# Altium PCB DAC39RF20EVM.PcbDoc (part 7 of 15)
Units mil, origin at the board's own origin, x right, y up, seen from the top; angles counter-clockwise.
Board outline 6200 x 2716.54 mil, 16 copper layers (Top Layer, L2 GND, L3 PWR, L4 GND, L5 PWR, L6 GND, L7 SIG, L8 GND, L9 GND, L10 SIG, L11 GND, L12 PWR, L13 GND, L14 PWR, L15 GND, Bottom Layer), stack 76.97 mil thick; 766 components, 495 nets, 3414 pads, 2373 vias.
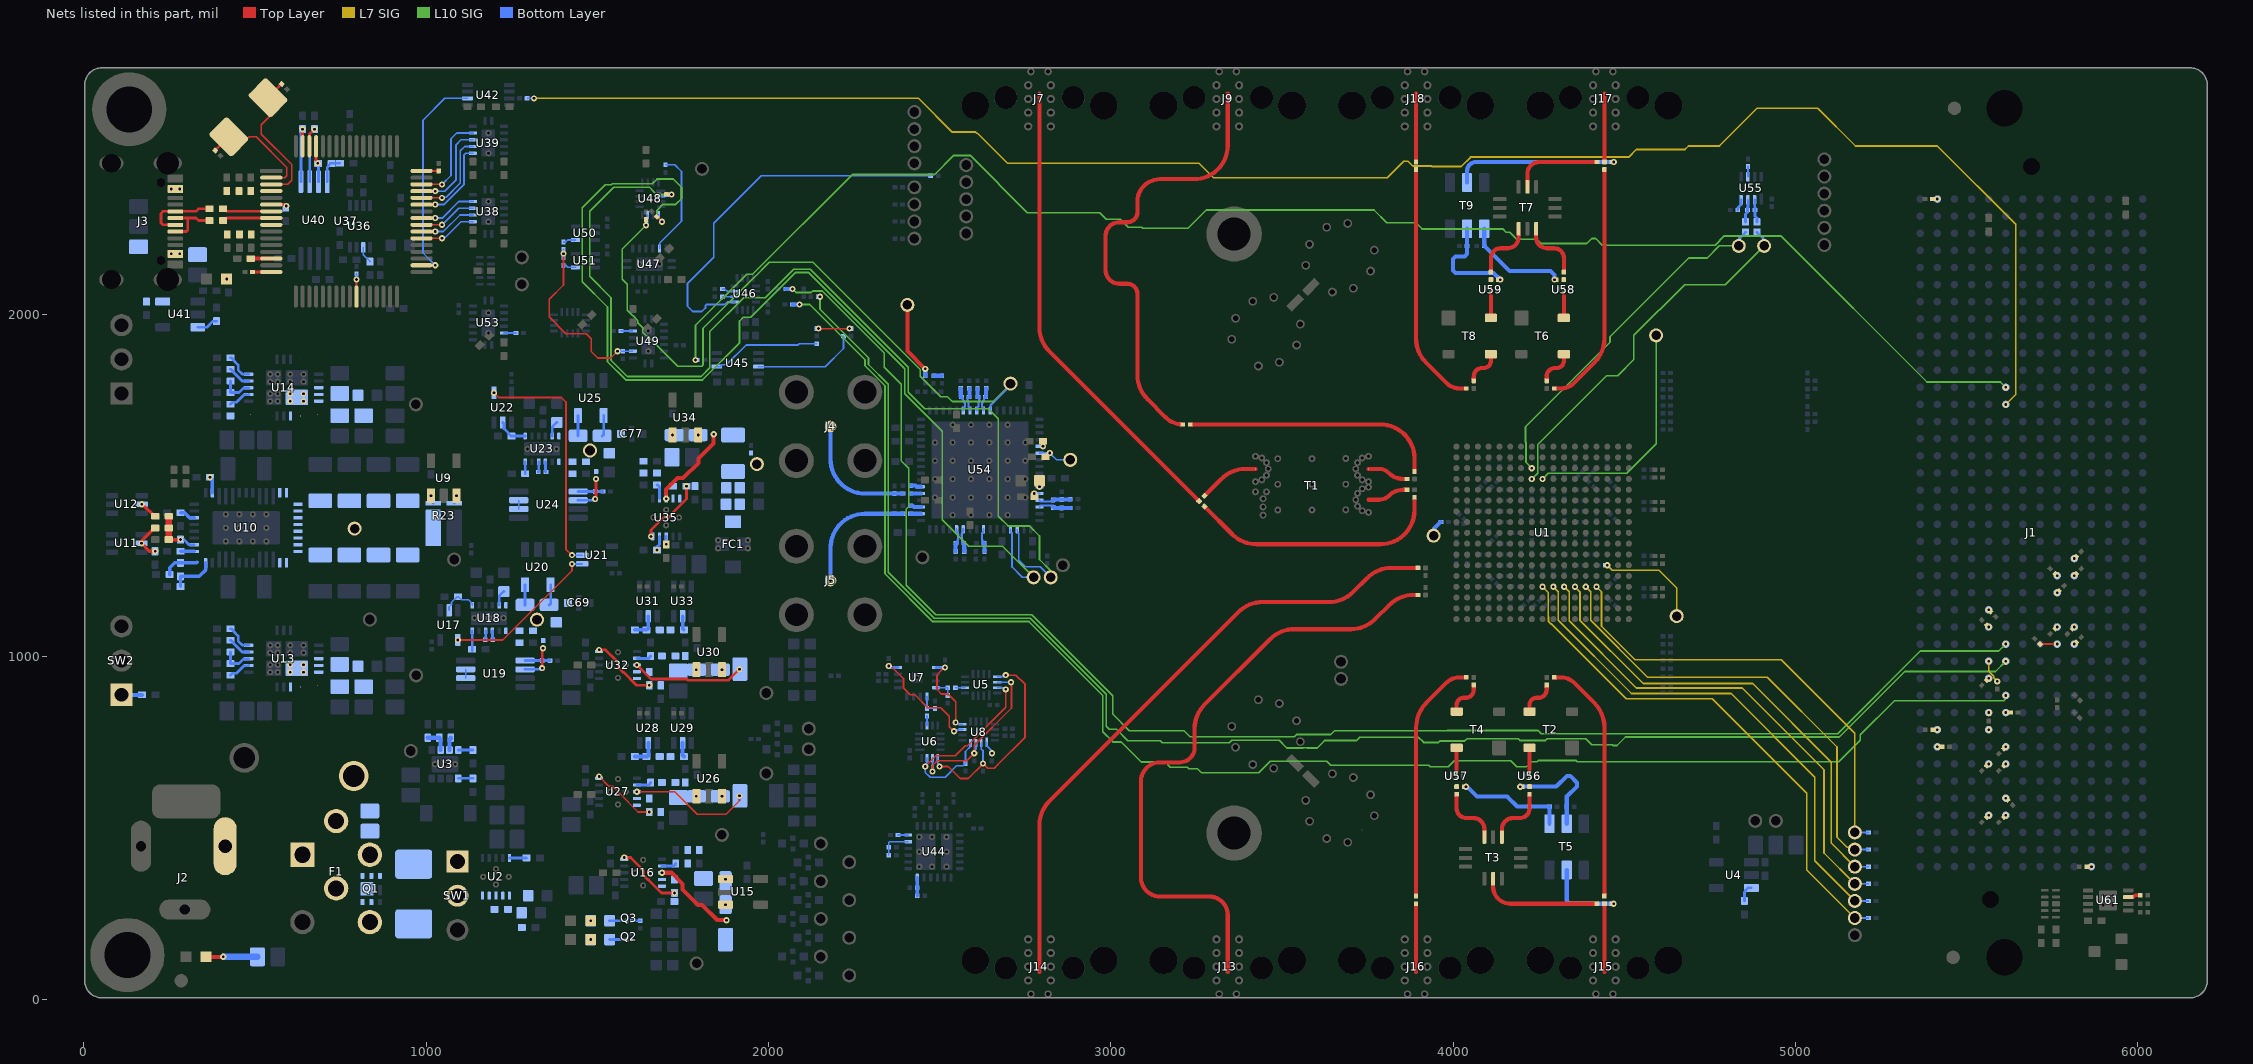
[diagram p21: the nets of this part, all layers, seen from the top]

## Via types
v1: diameter 18, hole 8, Top Layer to Bottom Layer, tented both sides, 2344 vias
v2: diameter 24, hole 12, Top Layer to Bottom Layer, tented both sides, 19 vias
v3: diameter 18, hole 8, Top Layer to Bottom Layer, tented bottom, 9 vias
v4: diameter 20, hole 10, Top Layer to Bottom Layer, tented both sides, 1 vias

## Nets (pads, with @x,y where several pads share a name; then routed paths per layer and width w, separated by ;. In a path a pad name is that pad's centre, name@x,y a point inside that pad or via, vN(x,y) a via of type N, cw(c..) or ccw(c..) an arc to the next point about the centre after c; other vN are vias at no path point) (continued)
LMK_DCLKOUT4_P: C166.2 R162.1 U54.24 | length 68.4
  Bottom Layer w6.3: R162.1@2627.86,1333.16 2626.85,1334.18 cw(c2630.65,1337.98) 2625.27,1337.98 2625.27,1339.13 ccw(c2621.96,1339.13) 2624.3,1341.47 cw(c2626.64,1343.81) 2623.33,1343.81 2623.33,1357.7 cw(c2631.34,1357.7) 2625.68,1363.37 ccw(c2620.02,1369.03) 2628.03,1369.03 U54.24@2628.03,1372.6
  Bottom Layer w12.1: R162.1@2627.87,1333.15 cw(c2621.01,1326.3) 2630.71,1326.3 C166.2@2630.71,1307.6
LMK_DCLKOUT6_N: C169.2 R163.2 U54.28 | length 68.2
  Bottom Layer w6.3: U54.28@2549.29,1372.6 2549.29,1369.03 ccw(c2557.3,1369.03) 2551.63,1363.37 cw(c2545.97,1357.7) 2553.98,1357.7 2553.98,1343.81 cw(c2550.67,1343.81) 2553.01,1341.47 ccw(c2555.35,1339.13) 2552.04,1339.13 2552.04,1337.98 cw(c2546.67,1337.98) R163.2@2550.47,1334.18
  Bottom Layer w12.1: C169.2@2546.61,1307.6 2546.61,1324.84 cw(c2559.81,1324.84) R163.2@2550.47,1334.18
LMK_DCLKOUT6_P: C168.2 R163.1 U54.27 | length 68.4
  Bottom Layer w6.3: R163.1@2568.81,1333.16 2567.79,1334.18 cw(c2571.59,1337.98) 2566.22,1337.98 2566.22,1339.13 ccw(c2562.91,1339.13) 2565.25,1341.47 cw(c2567.59,1343.81) 2564.28,1343.81 2564.28,1357.7 cw(c2572.29,1357.7) 2566.63,1363.37 ccw(c2560.96,1369.03) 2568.97,1369.03 U54.27@2568.97,1372.6
  Bottom Layer w12.1: R163.1@2568.81,1333.15 cw(c2561.96,1326.3) 2571.65,1326.3 C168.2@2571.65,1307.6
LMK_DCLKOUT10_N: C173.2 R164.2 U54.55 | length 70.6
  Bottom Layer w6.3: R164.2@2585.23,1759.06 2584.7,1759.06 2581.55,1755.91 2581.55,1747 2583.96,1744.59 2583.96,1730.64 2588.66,1725.95 U54.55@2588.66,1719.06
  Bottom Layer w12.1: R164.2@2585.23,1759.06 ccw(c2585.23,1760.56) 2586.73,1760.56 C173.2@2586.73,1784.06
LMK_DCLKOUT10_P: C172.2 R164.1 U54.54 | length 72.4
  Bottom Layer w6.3: R164.1@2563.58,1759.06 2563.97,1759.06 2567.12,1755.91 2567.12,1751.16 2571.25,1747.03 2571.25,1742.73 2573.66,1740.32 2573.66,1730.64 2568.97,1725.95 U54.54@2568.97,1719.06
  Bottom Layer w12.1: C172.2@2561.29,1784.06 2561.29,1760.95 ccw(c2563.18,1760.95) R164.1@2563.18,1759.06
LMK_SCLK: PP32.1 R142.1 U48.2 U54.19 | length 3121
  Top Layer w5: R142.1@1701.73,2350.62 v1(1716.73,2350.62)
  L10 SIG w5: v1(1716.73,2350.62) 1672.05,2350.62 1668.11,2354.56 1668.11,2355.69 1652.43,2371.37 1547.97,2371.37 1477.62,2301.02 1477.62,2111.24 1540.07,2048.79 1540.07,1866.08 1587.42,1818.73 1803.09,1818.73 1828.64,1844.29 1828.64,1950.25 1927.18,2048.79 1990.72,2048.79 2074.19,2132.26 2121.64,2132.26 2408.11,1845.79 2408.11,1772.88 2456.12,1724.87 2641.38,1724.87 2671.06,1695.18 2671.06,1410.97 2699.71,1382.33 2761.8,1382.33 2791.41,1352.72 2791.41,1284.15 2824.32,1251.24 PP32.1@2824.32,1232.14
  Bottom Layer w5: U48.2@1686.73,2345.62 1708.21,2345.62 1713.21,2350.62 v1(1716.73,2350.62) ; U54.19@2726.45,1372.6 2726.45,1365.71 2730.8,1361.37 2730.8,1282.26 2750.35,1262.71 2793.76,1262.71 PP32.1@2824.32,1232.14
LMK_SDCLKOUT1_N: C163.2 R158.2 R160.2 U54.14 | length 97.8
  Bottom Layer w6.3: U54.14@2791.41,1437.56 cw(c2795.35,1437.56) 2795.35,1441.5 2826.29,1441.5 cw(c2826.29,1436.38) 2831.29,1437.49 cw(c2826.29,1436.38) R158.2@2831.41,1436.38
  Bottom Layer w12.1: R158.2@2829.84,1438.74 ccw(c2839.17,1448.09) 2831.29,1437.49 ccw(c2839.17,1448.09) 2839.17,1434.88 C163.2@2881.41,1434.88
LMK_SDCLKOUT1_P: C162.2 R158.1 R159.2 U54.13 | length 97.8
  Bottom Layer w6.3: U54.13@2791.41,1457.25 ccw(c2795.35,1457.25) 2795.35,1453.3 2826.29,1453.3 ccw(c2826.29,1458.43) 2831.29,1457.32 ccw(c2826.29,1458.43) R158.1@2831.41,1458.43
  Bottom Layer w12.1: R158.1@2829.84,1456.07 cw(c2839.16,1446.74) 2831.29,1457.32 cw(c2839.16,1446.74) 2839.06,1459.93 cw(c2839.16,1446.74) 2839.16,1459.93 R159.2@2856.41,1459.93 C162.2@2881.41,1459.93
LMK_SDCLKOUT11_N: C175.2 R165.1 U54.57 | length 72.4
  Bottom Layer w6.3: U54.57@2628.03,1719.06 2628.03,1725.95 2623.33,1730.64 2623.33,1740.32 2625.75,1742.73 2625.75,1747.03 2629.88,1751.16 2629.88,1755.91 2633.03,1759.06 R165.1@2633.42,1759.06
  Bottom Layer w12.1: R165.1@2633.81,1759.06 ccw(c2633.81,1760.95) 2635.71,1760.95 C175.2@2635.71,1784.06
LMK_SDCLKOUT11_P: C174.2 R165.2 U54.56 | length 70.6
  Bottom Layer w6.3: U54.56@2608.34,1719.06 2608.34,1725.95 2613.03,1730.64 2613.03,1744.59 2615.45,1747 2615.45,1755.91 2612.3,1759.06 R165.2@2611.77,1759.06
  Bottom Layer w12.1: C174.2@2610.27,1784.06 2610.27,1760.56 ccw(c2611.77,1760.56) R165.2@2611.77,1759.06
LMK_SDI: PP33.1 R143.1 U48.5 U54.20 | length 3203.6
  Top Layer w5: R143.1@1673.86,2285.51 v1(1688.86,2270.51)
  L10 SIG w5: v1(1688.86,2270.51) 1674.51,2284.85 1674.51,2304.32 1691.57,2321.38 1729.38,2321.38 1745.94,2337.94 1745.94,2371.37 1721.87,2395.44 1674.51,2395.44 1660.45,2381.37 1543.83,2381.37 1541.39,2378.94 1522.97,2378.94 1456.1,2312.06 1456.1,2095.26 1529.79,2021.57 1529.79,1862.22 1583.27,1808.73 1807.23,1808.73 1915.46,1916.97 1915.46,1980.9 1926.52,1991.96 1948.03,1991.96 2078.33,2122.26 2117.5,2122.26 2398.11,1841.65 2398.11,1768.73 2507.7,1659.14 2507.7,1399.79 2584.39,1323.1 2683.36,1323.1 PP33.1@2774.32,1232.14
  Bottom Layer w5: U48.5@1678.86,2290.51 1678.86,2282.63 1688.86,2272.63 v1(1688.86,2270.51) ; U54.20@2706.77,1372.6 2706.77,1365.71 2711.11,1361.37 2711.11,1262.59 2741.56,1232.14 PP33.1@2774.32,1232.14
LMK_SDO: PP34.1 R144.1 U48.7 U54.58 | length 2026
  Top Layer w6.3: v1(1642.36,2260.51) R144.1@1642.36,2277.26
  L10 SIG w5: v1(1642.36,2260.51) 1642.1,2260.51 1572.89,2191.3 1572.89,2102.91 1587.39,2088.41 1587.39,2011.71 1603.01,1996.1 1604.65,1996.1 1618.33,1982.42 1618.33,1975.39 1632.44,1961.29 1632.44,1947.98 1643.13,1937.29 1645.59,1937.29 1734.45,1848.43 1804.5,1848.43 1808.64,1852.57 1808.64,1959.55 1956.54,2107.45 1957.55,2107.45 2002.37,2152.26 2129.93,2152.26 2443.17,1839.02 2443.17,1819.28 2502.89,1759.56 2522.63,1759.56 2536.66,1745.52 2655.61,1745.52 2706.77,1796.68 PP34.1@2706.77,1798.03
  Bottom Layer w5: v1(1642.36,2260.51) 1642.36,2264.02 1647.36,2269.02 U48.7@1647.36,2290.51
  Bottom Layer w6.3: U54.58@2647.71,1719.06 2648.23,1719.57 2648.23,1734.89 2706.77,1793.43 PP34.1@2706.77,1798.03
NetC1_1: C1.1 D2.2 F1.2 Q1.3 SW1.1
NetC1_2: C1.2 D2.1 F1.4 Q1.1 Q1.2 Q1.5 Q1.6 Q1.8
NetC4_2: C4.2 R1.1 R4.2 U2.2
NetC5_2: C5.2 U2.1
NetC10_2: C10.2 U3.8 | length 43
  Bottom Layer w8: U3.8@1093.48,727.63 C10.2@1136.48,727.63
NetC11_1: C11.1 R12.2 U7.4 | length 58
  Bottom Layer w5: U7.4@2488.63,909.89 R12.2@2523.63,909.89 C11.1@2523.63,886.89
NetC12_1: C12.1 R16.2 U7.5 | length 58
  Bottom Layer w5: U7.5@2463.04,884.3 R16.2@2463.04,849.3 C12.1@2486.04,849.3
NetC22_2: C22.2 C23.2 C24.2 C25.2 C27.2 C28.2 C29.2 C30.2 PP10.1 R23.4 U10.13 U10.14 U10.15 U10.16 U10.17 U10.18 U10.19 U10.20 U10.21 U10.22 U10.23 U10.24 U10.25 U10.26
NetC26_2: C26.2 U10.39 | length 40.3
  Bottom Layer w10: C26.2@282.52,1308.34 294.33,1308.34 294.98,1307.69 U10.39@322.52,1307.69
NetC31_2: C31.2 U10.44 | length 46.2
  Bottom Layer w10: C31.2@282.52,1420.71 294.33,1420.71 294.33,1420.53 308.74,1406.12 U10.44@322.52,1406.12
NetC34_2: C34.2 C35.2 C36.2 FB1.1 U13.10 U13.11 U13.12 U13.13 U13.14 U13.15 U13.27
NetC39_1: C39.1 U13.21 | length 64.7
  Bottom Layer w8: C39.1@428.75,946.11 434.53,951.9 445.59,951.9 467.5,973.81 480.64,973.81 U13.21@481.56,974.73
NetC42_2: C42.2 C43.2 C44.2 FB2.1 U14.10 U14.11 U14.12 U14.13 U14.14 U14.15 U14.27
NetC47_1: C47.1 U14.21 | length 64.7
  Bottom Layer w8: C47.1@428.75,1737.64 434.53,1743.42 445.59,1743.42 467.5,1765.34 480.64,1765.34 U14.21@481.56,1766.26
NetC52_2: C52.2 R46.1 R47.2 U15.1 U16.9 U16.10
  other v1: 1874.64,350.61
NetC58_2: C58.2 R49.2 U16.7 | length 44
  Bottom Layer w9: U16.7@1688.89,388.99 1723.55,388.99 1728.89,394.34 C58.2@1728.89,396.08
NetC68_1: C68.1 U18.10 | length 26.5
  Bottom Layer w8: C68.1@1172.67,1049.81 1172.67,1056.11 1173.86,1057.29 U18.10@1173.86,1075.81
NetC68_2: C68.2 U18.9 | length 26.5
  Bottom Layer w8: U18.9@1193.72,1075.81 1193.72,1057.29 1194.9,1056.11 C68.2@1194.9,1049.81
NetC69_1: C69.1 C70.2 PP23.1 R52.2 R53.2 R57.1 U20.4 | length 61.8
  Bottom Layer w8: R52.2@1359.26,1150.61 1363.59,1154.95 U20.4@1363.59,1210.61
NetC71_2: C71.2 U18.5 | length 46.4
  Bottom Layer w8: U18.5@1213.23,1150.61 1213.23,1174.18 1214.56,1175.52 1214.56,1178.87 1226.31,1190.61 C71.2@1227.3,1190.61
NetC76_1: C76.1 U23.10 | length 30.5
  Bottom Layer w8: C76.1@1327.49,1539.83 1328.67,1541.01 U23.10@1328.67,1569.83
NetC76_2: C76.2 U23.9 | length 30.5
  Bottom Layer w8: U23.9@1348.36,1569.83 1348.36,1541.01 C76.2@1349.54,1539.83
NetC77_1: C77.1 C78.2 PP24.1 R60.2 R61.2 R65.1 U25.4 | length 61.8
  Bottom Layer w8: R60.2@1514.07,1644.63 1518.4,1648.96 U25.4@1518.4,1704.63
NetC79_2: C79.2 U23.5 | length 46.4
  Bottom Layer w8: U23.5@1368.04,1644.63 1368.04,1668.19 1369.38,1669.53 1369.38,1672.88 1381.13,1684.63 C79.2@1382.11,1684.63
NetC84_2: C84.2 R70.1 R71.2 U26.1 U27.9 U27.10
  other v1: 1789.17,592.47
NetC90_2: C90.2 R72.1 R75.2 R77.2 U27.7 | length 44
  Bottom Layer w9: U27.7@1615.52,625.54 1650.18,625.54 1655.52,630.88 C90.2@1655.52,632.63
NetC94_2: C94.2 R83.1 R84.2 U30.1 U32.9 U32.10
  other v1: 1789.17,962.47
NetC99_2: C99.2 R80.1 R85.2 R87.2 U32.7 | length 44
  Bottom Layer w9: U32.7@1615.52,995.54 1650.18,995.54 1655.52,1000.88 C99.2@1655.52,1002.63
NetC107_2: C107.2 R92.1 R93.2 U34.1 U35.9 U35.10
  other v1: 1719.79,1647.65
NetC108_2: C108.2 C109.2 C110.2 C111.2 FB6.2 FC1.1 PP29.1 R89.1
NetC112_2: C112.2 R95.2 U35.7 | length 44
  Bottom Layer w9: C112.2@1674.32,1501.9 1676.06,1501.9 1681.4,1496.56 U35.7@1681.4,1461.9
NetC114_2: C114.2 C115.2 FB7.2 U37.9
NetC116_2: C116.2 C117.2 FB8.2 U37.4
NetC129_2: C129.2 U37.2 Y1.1 | length 338.6
  Top Layer w5: Y1.1@423.71,2518.95 428.71,2513.95 478.07,2513.95 483.07,2518.95 503.21,2518.95 592.88,2429.29 592.88,2405.47 586.97,2399.56 U37.2@547.59,2399.56
  Top Layer w8: C129.2@383.71,2478.95 Y1.1@423.71,2518.95
NetC130_2: C130.2 U37.3 Y1.2 | length 411.4
  Top Layer w5: Y1.2@537.85,2633.09 542.85,2628.09 542.85,2578.73 518.5,2554.38 518.5,2526.75 607.21,2438.03 607.21,2391.69 595.4,2379.88 U37.3@547.59,2379.88
  Top Layer w8: Y1.2@537.85,2633.09 C130.2@577.85,2673.09
NetC133_2: C133.2 R115.2 U41.5
NetC160_1: C160.1 J4.1 R157.2 | length 364.7
  Bottom Layer w12.1: v1(2181.22,1672.88) 2181.22,1576.93 ccw(c2281.22,1576.93) 2281.22,1476.93 R157.2@2367.91,1476.93 C160.1@2392.91,1476.93
NetC160_2: C160.2 U54.37 | length 30
  Bottom Layer w12.1: C160.2@2414.96,1476.93 U54.37@2444.96,1476.93
NetC161_2: C161.2 U54.38 | length 31.4
  Bottom Layer w12.1: C161.2@2414.96,1499.98 2429.78,1499.98 2433.14,1496.62 U54.38@2444.96,1496.62
NetC164_2: C164.2 U54.35 | length 31.4
  Bottom Layer w12.1: C164.2@2414.96,1440.92 2422.04,1440.92 2425.4,1437.56 U54.35@2444.96,1437.56
NetC165_1: C165.1 J5.1 R161.2 | length 363.8
  Bottom Layer w12.1: v1(2181.22,1222.88) 2181.22,1317.88 cw(c2281.22,1317.88) 2281.22,1417.88 R161.2@2367.91,1417.88 C165.1@2392.91,1417.88
NetC165_2: C165.2 U54.34 | length 30
  Bottom Layer w12.1: C165.2@2414.96,1417.88 U54.34@2444.96,1417.88
NetC170_1: C170.1 PP40.1 | length 228.3
  Top Layer w12.1: PP40.1@2405.59,2027.82 2405.59,1893.19 v1(2457.67,1841.11)
  Bottom Layer w12.1: C170.1@2457.67,1821.11 v1(2457.67,1841.11)
NetC171_1: C171.1 R168.2 | length 25
  Bottom Layer w12.1: C171.1@2481.85,1821.11 R168.2@2506.85,1821.11
NetC176_2: C176.2 U54.11 | length 18
  Top Layer w10: v1(2791.41,1496.62) 2791.41,1514.36 C176.2@2791.7,1514.36
NetC177_1: C177.1 U54.12 | length 24.7
  Top Layer w6.3: v1(2776.41,1476.93) cw(c2776.41,1475.97) 2777.37,1475.97 C177.1@2777.37,1467.83
  Bottom Layer w6.3: v1(2776.41,1476.93) U54.12@2791.41,1476.93
NetC182_1: C182.1 C183.1 | length 742.1
  Top Layer w12.1: 3354.38,1357.99 ccw(c3425.1,1428.7) 3425.1,1328.7 3786.85,1328.7
  Top Layer w12.3: C182.1@3273.32,1439.06 3354.38,1357.99 ; 3786.85,1328.7 ccw(c3786.85,1428.7) 3886.85,1428.7 C183.1@3886.85,1458.82
NetC182_2: C182.2 C184.2 J7.1 | length 1379.3
  Top Layer w12.1: J7.1@2791.51,2645.14 2791.51,1962.29 ccw(c2891.51,1962.29) 2820.8,1891.58 C182.2@3257.73,1454.65
NetC184_1: C184.1 T1.1 | length 177.4
  Top Layer w12.3: C184.1@3273.32,1470.24 3322.49,1519.41 cw(c3393.2,1448.7) 3393.2,1548.7 T1.1@3422.48,1548.7
NetC186_2: C186.2 T1.2 | length 120.1
  Top Layer w12.1: T1.2@3752.71,1458.7 3783.45,1458.7 ccw(c3783.45,1498.96) 3811.92,1470.49 cw(c3854.07,1428.34) 3854.07,1487.95 C186.2@3864.8,1487.95 C186.2@3865.04,1487.95
NetC190_2: C190.2 T1.3 | length 120.1
  Top Layer w12.1: T1.3@3752.48,1548.7 3783.22,1548.7 cw(c3783.22,1508.44) 3811.68,1536.91 ccw(c3853.84,1579.06) 3853.84,1519.45 C190.2@3864.8,1519.45
NetC192_1: C192.1 C197.1 | length 749.2
  Top Layer w12.1: C197.1@3232.04,1678.7 3665.6,1678.7
  Top Layer w12.3: 3665.6,1678.7 3786.98,1678.7 cw(c3786.98,1578.7) 3886.98,1578.7 C192.1@3886.98,1548.58 ; C192.1@3886.85,1541.5 C192.1@3886.85,1548.58
NetC197_2: C197.2 J9.1 | length 1351
  Top Layer w12.1: C197.2@3209.99,1678.7 cw(c3209.99,1749.79) 3159.72,1699.52 3106.8,1752.44 cw(c3177.51,1823.16) 3077.51,1823.16 3077.51,2060.35 ccw(c3048.22,2060.35) 3048.22,2089.64 3024.6,2089.64 cw(c3024.6,2129.64) 2984.6,2129.64 2984.6,2229.4 cw(c3024.6,2229.4) 3024.6,2269.4 3048.22,2269.4 ccw(c3048.22,2298.69) 3077.51,2298.69 3077.51,2329.31 cw(c3143.34,2329.31) 3143.34,2395.14 3243.01,2395.14 ccw(c3243.01,2493.64) 3341.51,2493.64 J9.1@3341.51,2645.14
NetC218_1: C218.1 R180.2 U55.3 | length 84.7
  Bottom Layer w5: C218.1@4859.56,2305.14 4859.56,2320.18 4860.74,2321.36 U55.3@4860.74,2335.14
  Bottom Layer w8: R180.2@4853.56,2270.14 4853.56,2292.84 4859.56,2298.84 C218.1@4859.56,2305.14 4859.56,2311.44 4860.74,2312.62 U55.3@4860.74,2321.36
NetC218_2: C218.2 R178.2 U55.2 | length 68
  Bottom Layer w8: U55.2@4880.43,2335.14 4880.43,2312.62 4881.61,2311.44 C218.2@4881.61,2305.14 4881.61,2287.16 4887.61,2281.16 R178.2@4887.61,2270.14
NetC220_1: C220.1 T3.1 | length 179.8
  Top Layer w12.1: T3.1@4142.1,473.58 4142.1,496.84 cw(c4174.03,496.84) 4174.03,528.77 4194.14,528.77 ccw(c4194.14,557.64) 4223.02,557.64 C220.1@4223.02,598.58
NetC220_2: C220.2 C222.2 U56.2
NetC221_1: C221.1 C223.1 J15.1 R184.1 | length 200
  Top Layer w12.1: J15.1@4441.51,78.8 C221.1@4441.51,278.8
NetC221_2: C221.2 T3.8 | length 354.2
  Top Layer w12.1: T3.8@4116.51,351.54 4116.51,328.8 ccw(c4166.51,328.8) 4166.51,278.8 C221.2@4419.46,278.8
NetC222_1: C222.1 C227.1 T5.2 | length 323.6
  Top Layer w8: v1(4195.97,620.63) C222.1@4200.97,620.63
  Bottom Layer w12.1: v1(4195.97,620.63) 4300.83,620.63 4331.88,651.69 4341.91,651.69 4361.48,632.11 4361.48,621.55 4331.48,591.55 C227.1@4331.48,562.45 T5.2@4331.48,512.45
NetC223_2: C223.2 T5.5 | length 235.3
  Top Layer w8: C223.2@4463.56,278.8 v1(4468.56,278.8)
  Bottom Layer w12.1: T5.5@4331.48,377.41 4331.48,291.39 ccw(c4344.08,291.39) 4344.08,278.8 v1(4468.56,278.8)
NetC224_1: C224.1 T3.3 | length 179.8
  Top Layer w12.1: C224.1@4010,598.58 4010,557.64 ccw(c4038.87,557.64) 4038.87,528.77 4058.99,528.77 cw(c4058.99,496.84) 4090.92,496.84 T3.3@4090.92,473.58
NetC224_2: C224.2 C225.2 U57.2
NetC225_1: C225.1 C226.1 T5.1 | length 323.5
  Top Layer w8: C225.1@4032.05,620.63 v1(4037.05,620.63)
  Bottom Layer w12.1: v1(4037.05,620.63) 4038.64,620.63 4041.59,617.68 4043.53,617.68 4069.5,591.71 4157.61,591.71 4186.88,562.45 C226.1@4281.48,562.45 T5.1@4281.48,512.45
NetC228_1: C228.1 T7.3 | length 179.8
  Top Layer w12.1: T7.3@4242.1,2248.63 4242.1,2225.37 ccw(c4274.03,2225.37) 4274.03,2193.44 4294.14,2193.44 cw(c4294.14,2164.57) 4323.02,2164.57 C228.1@4323.02,2123.63
NetC228_2: C228.2 C230.2 U58.2
NetC229_1: C229.1 C231.1 J17.1 R190.1 | length 199.8
  Top Layer w12.1: C229.1@4441.51,2445.37 4441.51,2475.37 J17.1@4441.51,2645.14
NetC229_2: C229.2 T7.8 | length 260.9
  Top Layer w12.1: T7.8@4216.51,2372.26 4216.51,2410.9 cw(c4250.74,2410.9) 4250.74,2445.14 4389.23,2445.14 C229.2@4419.23,2445.14
NetC230_1: C230.1 C235.1 T9.1 | length 309.1
  Top Layer w8: v1(4295.74,2101.58) C230.1@4300.74,2101.58
  Bottom Layer w12.1: T9.1@4090.52,2250.1 C235.1@4090.52,2200.1 4091.31,2200.1 4164.89,2126.52 4284.54,2126.52 4295.51,2115.55 4295.51,2101.81 v1(4295.74,2101.58)
NetC231_2: C231.2 T9.5 | length 482.1
  Top Layer w8: C231.2@4463.79,2445.14 v1(4468.79,2445.14)
  Bottom Layer w12.1: T9.5@4040.52,2385.14 4040.52,2419.23 cw(c4066.43,2419.23) 4066.43,2445.14 v1(4468.79,2445.14)
NetC232_1: C232.1 T7.1 | length 179.8
  Top Layer w12.1: C232.1@4110,2123.63 4110,2164.57 cw(c4138.87,2164.57) 4138.87,2193.44 4158.99,2193.44 ccw(c4158.99,2225.37) 4190.92,2225.37 T7.1@4190.92,2248.63
NetC232_2: C232.2 C233.2 U59.2
NetC233_1: C233.1 C234.1 T9.2 | length 308.7
  Top Layer w8: C233.1@4132.28,2101.58 v1(4137.28,2101.58)
  Bottom Layer w12.1: T9.2@4040.52,2250.1 C234.1@4040.52,2200.1 4040.52,2176.18 4033.44,2169.09 4006.47,2169.09 3999.38,2162 3999.38,2128.08 4006.47,2120.99 4117.87,2120.99 v1(4137.28,2101.58)
NetD1_2: D1.2 R3.2 | length 150
  Top Layer w12: D1.2@357.27,123.65 v1(407.27,123.65)
  Bottom Layer w18: v1(407.27,123.65) R3.2@507.27,123.65
NetD4_2: D4.2 R108.2 | length 5
  Bottom Layer w12.1: v1(417.59,2103.8) R108.2@422.59,2103.8
NetD6_1: D6.1 R235.1
  other v1: 1480.75,174.11
NetD7_1: D7.1 R236.1
  other v1: 1480.75,229.11
NetF1_1: F1.1 J2.1 TP1.1
NetFB3_1: FB3.1 R46.2 U15.3 U16.8 | length 255.5
  Top Layer w12: v1(1688.82,369.31) 1716.19,369.31 1748.9,336.6 1748.9,320.03 1793.58,275.35 1806.26,275.35 1850.23,231.38 1875.85,231.38 v1(1877,230.23)
  other v1: 1874.64,275.81
NetFB4_1: FB4.1 R70.2 U26.3 U27.8 | length 357.3
  Top Layer w5: v1(1615.45,605.86) 1726.13,605.86 1791.54,540.44 1875.85,540.44 1915.52,580.11 v1(1915.52,593.85)
  other v1: 1863.97,592.47
NetFB5_1: FB5.1 R83.2 U30.3 U32.8 | length 331.6
  Top Layer w8: v1(1615.45,975.86) 1656.51,934.8 1761.05,934.8 1764.03,931.82 1883.49,931.82 v1(1915.52,963.85)
  other v1: 1863.97,962.47
NetFB6_1: FB6.1 R92.2 U34.3 U35.8 | length 255.5
  Top Layer w12: v1(1701.09,1461.83) 1701.09,1489.2 1733.8,1521.91 1750.36,1521.91 1795.05,1566.59 1795.05,1579.27 1839.01,1623.24 1839.01,1648.86 v1(1840.16,1650.01)
  other v1: 1794.59,1647.65
NetJ1_B40: J1.B40 R198.2 | length 13.3
  Top Layer w10: R198.2@5850.72,387.07 v1(5864.01,387.07)
NetJ1_C22: J1.C22 R199.2 | length 6.7
  Top Layer w5: v1(5814.01,1287.07) R199.2@5818.72,1291.77
NetJ1_C23: J1.C23 R201.2 | length 6.7
  Top Layer w5: v1(5814.01,1237.07) R201.2@5818.72,1241.77
NetJ1_C26: J1.C26 R204.2 | length 6.7
  Top Layer w5: R204.2@5809.31,1082.36 v3(5814.01,1087.07)
NetJ1_C27: J1.C27 R206.2 | length 6.7
  Top Layer w5: v3(5814.01,1037.07) R206.2@5818.72,1041.77
NetJ1_D23: J1.D23 R200.2 | length 7.1
  Top Layer w5: R200.2@5759.31,1241.77 v1(5764.01,1237.07) v1@5764.32,1236.76
NetJ1_D24: J1.D24 R202.2 | length 6.7
  Top Layer w5: v1(5764.01,1187.07) R202.2@5768.72,1191.77
NetJ1_D26: J1.D26 R203.2 | length 6.7
  Top Layer w5: R203.2@5759.31,1082.36 v3(5764.01,1087.07)
NetJ1_D27: J1.D27 R205.2 | length 50
  Top Layer w5: R205.2@5714.01,1037.07 v3(5764.01,1037.07)
NetJ1_G12: J1.G12 R210.2 | length 4497.7
  L10 SIG w5: v1(1786.93,1867.08) 1786.93,1968.28 1936.09,2117.45 1953.41,2117.45 2244.41,2408.45 2484.86,2408.45 2540.87,2464.45 2589.11,2464.45 2756.22,2297.34 2967.66,2297.34 2986.89,2278.11 3027.15,2278.11 3051.02,2254.24 3090.17,2254.24 3092.64,2251.77 3225.09,2251.77 3278.31,2304.98 3768.69,2304.98 3805.48,2268.2 3890.42,2268.2 3908.78,2249.84 4144.47,2249.84 4154.29,2240.02 4164.91,2240.02 4185.42,2219.51 4244.48,2219.51 4256.73,2207.26 4389.98,2207.26 4404.48,2221.77 4416.5,2221.77 4435.78,2202.49 4765.25,2202.49 4792.08,2229.32 4957.1,2229.32 5383.62,1802.8 5598.28,1802.8 v1(5614.01,1787.07)
  Bottom Layer w8: v1(1786.93,1867.08) R210.2@1791.93,1867.08
NetJ1_G13: J1.G13 R211.2 | length 5219.4
  L7 SIG w5: v1(1314.92,2631.1) 2437.99,2631.1 2536.43,2532.66 2604.56,2532.66 2608.12,2529.1 2610.38,2529.1 2698.15,2441.34 3257.52,2441.34 3299.59,2399.27 3306.32,2399.27 3306.4,2399.34 3807.64,2399.34 3855.87,2447.57 3867.88,2447.57 3881.97,2433.49 3936.46,2433.49 3937.83,2432.11 4023.19,2432.11 4050.71,2459.64 4512.94,2459.64 4535.37,2482.07 4677.11,2482.07 4687.11,2492.07 4777.45,2492.07 4887.45,2602.07 5064.84,2602.07 5174.84,2492.07 5414.01,2492.07 5643.09,2262.99 5643.09,1766.14 v3(5614.01,1737.07)
  Bottom Layer w5: R211.2@1294.92,2631.1 v1(1314.92,2631.1)
NetJ1_G27: J1.G27 R212.2 | length 4626
  L10 SIG w5: v1(2070.2,2074.43) 2080.25,2064.37 2124.97,2064.37 2128.92,2068.33 2157.29,2068.33 2338.39,1887.23 2338.39,1845.52 2388.11,1795.8 2388.11,1571.77 2409.41,1550.48 2409.41,1439.09 2401.94,1431.62 2401.94,1209.24 2488.3,1122.88 2768.95,1122.88 3005.65,886.18 3005.65,832.71 3054.17,784.19 3213.52,784.19 3231.06,766.64 3535.9,766.64 3542.01,772.75 3641.53,772.75 3653.08,784.3 3843.95,784.3 3844.2,784.05 3982.67,784.05 3983.38,784.76 4248.3,784.76 4257.47,775.59 5122.99,775.59 5364.13,1016.73 5593.67,1016.73 v1(5614.01,1037.07)
  Bottom Layer w12: R212.2@2050.2,2074.43 v1(2070.2,2074.43)
NetJ1_G28: J1.G28 R213.2 | length 4567.9
  L10 SIG w5: v1(2150.2,2051.83) 2150.2,2014.8 2291.99,1873.01 2291.99,1853.93 2350.13,1795.8 2350.13,1246.91 2484.16,1112.88 2764.81,1112.88 2986.61,891.08 2986.61,796.87 2995.1,788.37 3016.47,788.37 3049.65,755.19 3144.02,755.19 3149.97,749.23 3345.89,749.23 3352.7,756.04 3491.81,756.04 3514.08,733.78 3561.55,733.78 3561.93,734.16 3573.94,734.16 3574.33,733.78 3602.56,733.78 3624.02,755.24 3717.44,755.24 3727.25,765.05 3898.22,765.05 3913.38,749.89 3956.88,749.89 3961.3,754.32 4033.84,754.32 4040.12,760.59 4190.37,760.59 4195.2,755.76 4269.56,755.76 4274.39,760.59 4387.1,760.59 4404.48,743.21 4464.4,743.21 4466.52,741.09 4478.53,741.09 4503.03,765.59 5127.13,765.59 5318.46,956.92 5583.86,956.92 v1(5614.01,987.07)
  Bottom Layer w12: R213.2@2145.2,2051.83 v1(2150.2,2051.83)
NetJ1_G30: J1.G30 R214.2 | length 4644.5
  L10 SIG w5: v1(2090.2,2029.23) 2120.77,2029.23 2281.99,1868.01 2281.99,1849.79 2340.13,1791.65 2340.13,1242.77 2480.02,1102.88 2760.67,1102.88 2976.61,886.93 2976.61,780.86 3006.5,750.97 3030.61,750.97 3088.91,692.67 3158.43,692.67 3173.86,677.24 3223.82,677.24 3227.85,673.21 3252.97,673.21 3264.8,661.38 3431.73,661.38 3465.15,694.8 3630.23,694.8 3642.13,682.89 3928.77,682.89 3932.9,678.76 3984.99,678.76 4002.53,696.3 4168.45,696.3 4185.99,678.76 4214.24,678.76 4228.57,693.09 4244.81,693.09 4249.07,697.34 4358.11,697.34 4362.36,693.09 5126.39,693.09 5189.26,755.96 5189.26,771.82 5289.02,871.57 5608.2,871.57 5612.19,875.56 5612.19,885.24 v1(5614.01,887.07)
  Bottom Layer w12: R214.2@2070.2,2029.23 v1(2090.2,2029.23)
NetJ1_G31: J1.G31 R215.2 | length 13.9
  Top Layer w5: v1(5614.01,837.07) R215.2@5627.91,837.07
NetJ1_G33: J1.G33 R216.2 | length 6.7
  Top Layer w5: R216.2@5609.31,732.36 v1(5614.01,737.07)
NetJ1_G34: J1.G34 R217.2 | length 6.7
  Top Layer w5: R217.2@5609.31,682.36 v1(5614.01,687.07)
NetJ1_G36: J1.G36 R218.2 | length 6.7
  Top Layer w5: v1(5614.01,587.07) R218.2@5618.72,582.36
NetJ1_G37: J1.G37 R219.2 | length 6.7
  Top Layer w5: R219.2@5609.31,532.36 v1(5614.01,537.07)
NetJ1_H25: J1.H25 R221.2 | length 6.7
  Top Layer w5: v1(5564.01,1137.07) R221.2@5568.72,1132.36
NetJ1_H26: J1.H26 R222.2 | length 6.7
  Top Layer w5: R222.2@5559.31,1091.77 v1(5564.01,1087.07)
NetJ1_H28: J1.H28 R223.2 | length 69.2
  L7 SIG w5: v1(5564.01,987.07) 5564.01,957.57 5578.51,943.07 5578.51,938.78 5589.01,928.28 v1(5589.01,928.22)
NetJ1_H29: J1.H29 R224.2 | length 6.7
  Top Layer w5: R224.2@5559.31,932.36 v1(5564.01,937.07)
NetJ1_H31: J1.H31 R225.2
  other v1: 5564.01,837.07
NetJ1_H32: J1.H32 R226.2
  other v1: 5564.01,787.07
NetJ1_H34: J1.H34 R227.2 | length 6.7
  Top Layer w5: R227.2@5559.31,682.36 v1(5564.01,687.07)
NetJ1_H37: J1.H37 R228.2 | length 6.7
  Top Layer w5: R228.2@5559.31,532.36 v1(5564.01,537.07)
NetJ1_L1: J1.L1 R230.2 | length 14
  Top Layer w10: R230.2@5400.04,2337.07 v1(5414.01,2337.07)
NetJ1_L32: J1.L32 R231.2 | length 13.3
  Top Layer w10: R231.2@5400.72,787.07 v1(5414.01,787.07)
NetJ1_L33: J1.L33 R232.2 | length 14
  Top Layer w10: v1(5414.01,737.07) R232.2@5427.99,737.07
NetJ3_A4,B4: J3.A4 J3.B4 R104.1
  other v1: 255.25,2177.12 280.25,2177.12 255.25,2366.1 280.25,2366.1
NetJ3_A6: J3.A6 J3.B6 R109.1 | length 175.9
  Top Layer w8: J3.B6@267.75,2242.08 299.32,2242.08 304,2246.77 304,2281.45 ; J3.A6@267.75,2281.45 304,2281.45 ; R109.1@367.75,2274.05 334.91,2274.05 327.51,2281.45 304,2281.45
NetJ3_A7: J3.A7 J3.B7 R106.1 | length 220
  Top Layer w8: J3.B7@263.22,2301.14 231.5,2301.14 225.43,2295.07 225.43,2267.84 231.5,2261.77 J3.A7@267.75,2261.77 ; J3.B7@263.22,2301.14 J3.B7@267.75,2301.14 327.74,2301.14 335.15,2308.54 R106.1@367.75,2308.54
NetJ13_1: J13.1 R172.2 | length 1853.1
  Top Layer w12.1: J13.1@3341.51,78.8 3341.51,245.8 ccw(c3287.61,245.8) 3287.61,299.7 3143.96,299.7 cw(c3143.96,355.87) 3087.79,355.87 3087.79,635.66 cw(c3143.87,635.66) 3143.87,691.75 3201.77,691.75 ccw(c3201.77,734.47) 3244.49,734.47 3244.49,789.47 cw(c3344.49,789.47) 3273.78,860.18 3464.94,1051.34 cw(c3535.65,980.63) 3527.48,1080.29 3700.75,1080.29 3701.08,1080.63 ccw(c3701.08,1180.63) 3771.8,1109.92 3813.22,1151.34 cw(c3883.93,1080.63) 3883.93,1180.63 R172.2@3896.98,1180.63
NetJ14_1: J14.1 R174.2 | length 1853.1
  Top Layer w12.1: J14.1@2791.51,78.8 2791.51,507.98 cw(c2891.51,507.98) 2820.8,578.69 3372.66,1130.56 cw(c3443.37,1059.85) 3443.37,1159.85 3636.82,1159.85 ccw(c3636.82,1259.85) 3707.53,1189.14 3748.95,1230.56 cw(c3819.66,1159.85) 3819.66,1259.85 R174.2@3896.98,1259.85
NetJ16_1: J16.1 R185.2 | length 200
  Top Layer w12.1: J16.1@3891.51,78.8 R185.2@3891.51,278.8
NetJ18_1: J18.1 R191.2 | length 200
  Top Layer w12.1: R191.2@3891.51,2445.14 J18.1@3891.51,2645.14
NetPP46_1: PP46.1 R170.2 U54.6 | length 115.3
  Top Layer w5: R170.2@2808.65,1584.53 2810.61,1584.53 2821.13,1595.04 v1(2821.41,1595.04)
  Bottom Layer w5: U54.6@2791.41,1595.04 v1(2821.41,1595.04) 2841.1,1575.36 PP46.1@2881.41,1575.36
NetPP48_1: PP48.1 R243.2 U1.D4 | length 1320.6
  L7 SIG w5: v1(4418.48,1204.49) 4432.98,1189.99 4432.98,1089.14 4530.92,991.19 4958.49,991.19 5173.01,776.68 PP48.1@5173.01,486.94
  Bottom Layer w5: PP48.1@5173.01,486.94 R243.2@5213.01,486.94
NetPP49_1: PP49.1 R244.2 U1.D9 | length 1533.2
  L7 SIG w5: v1(4261,1204.49) 4277.5,1187.99 4277.5,1116.83 4277.99,1116.34 4277.99,1103.99 4286.49,1095.5 4287.59,1095.5 4505.6,877.49 4757.02,877.49 5032.61,601.91 5032.61,377.34 PP49.1@5173.01,236.94
  Bottom Layer w5: PP49.1@5173.01,236.94 R244.2@5213.01,236.94
NetPP50_1: PP50.1 R245.2 U1.D8 | length 1492.6
  L7 SIG w5: v1(4292.49,1204.49) 4306.99,1189.99 4306.99,1106.49 4520.9,892.59 4811.64,892.59 5055.7,648.53 5055.7,404.25 PP50.1@5173.01,286.94
  Bottom Layer w5: PP50.1@5173.01,286.94 R245.2@5213.01,286.94
NetPP51_1: PP51.1 R246.2 U1.D7 | length 1440.3
  L7 SIG w5: v1(4323.99,1204.49) 4338.49,1189.99 4338.49,1105.57 4535.08,908.98 4844.27,908.98 5083.05,670.21 5083.05,426.9 PP51.1@5173.01,336.94
  Bottom Layer w5: PP51.1@5173.01,336.94 R246.2@5213.01,336.94
NetPP52_1: PP52.1 R247.2 U1.D6 | length 1383.6
  L7 SIG w5: v1(4355.48,1204.49) 4369.98,1189.99 4369.98,1106.49 4554.65,921.83 4874.58,921.83 5103.94,692.46 5103.94,456 PP52.1@5173.01,386.94
  Bottom Layer w5: PP52.1@5173.01,386.94 R247.2@5213.01,386.94
NetPP53_1: PP53.1 R248.2 U1.D5 | length 1347.2
  L7 SIG w5: v1(4386.98,1204.49) 4401.48,1189.99 4401.48,1106.49 4567.43,940.54 4917.01,940.54 5121.14,736.42 5121.14,473.01 5150.32,443.83 5166.12,443.83 PP53.1@5173.01,436.94
  Bottom Layer w5: PP53.1@5173.01,436.94 R248.2@5213.01,436.94
NetPP55_1: PP55.1 R178.1 U1.P10 | length 1099.2
  L10 SIG w5: v1(4229.5,1519.45) 4246.5,1536.44 4246.5,1619.94 4447.76,1821.21 4480.39,1821.21 4527.61,1868.43 4527.61,1938.8 4675.87,2087.07 4794.93,2087.07 PP55.1@4908.08,2200.21
  Bottom Layer w8: R178.1@4887.61,2240.21 4887.61,2239.43 4905.73,2221.31 4905.73,2202.57 PP55.1@4908.08,2200.21
NetPP57_1: PP57.1 R179.2 | length 49
  Bottom Layer w12.1: PP57.1@3942.61,1353.8 3944.43,1355.62 3944.43,1374.7 3963.19,1393.46 R179.2@3963.98,1393.46
NetPP58_1: PP58.1 U1.P9 | length 691
  L10 SIG w5: v1(4261,1519.45) 4277.99,1536.44 4507.17,1536.44 4592.61,1621.88 PP58.1@4592.61,1938.8
NetPP60_1: PP60.1 R180.1 U1.R10 | length 1028.1
  L10 SIG w5: v1(4229.5,1550.94) 4212.5,1567.94 4212.5,1625.83 4211,1627.34 4211,1671.58 4457.84,1918.41 4457.84,1934.99 4687.61,2164.76 4741.67,2164.76 4777.12,2200.21 PP60.1@4834.03,2200.21
  Bottom Layer w8: PP60.1@4834.03,2200.21 4835.44,2201.62 4835.44,2221.31 4853.56,2239.43 R180.1@4853.56,2240.21
NetPP62_1: PP62.1 R181.2 U1.F3 | length 317.1
  L7 SIG w5: v1(4449.97,1267.48) 4464.84,1252.61 4600.98,1252.61 4652.61,1200.98 PP62.1@4652.61,1118.8
  Bottom Layer w5: R181.2@4445.24,1267.48 v1(4449.97,1267.48)
NetQ2_2: Q2.2@1585.87,174.11 R235.2 | length 50
  Bottom Layer w8: R235.2@1535.87,174.11 Q2.2@1585.87,174.11
NetQ3_1: Q3.1@1599.65,229.11 R249.1 | length 26
  Bottom Layer w8: Q3.1@1599.65,229.11 1619.22,229.11 1619.22,229.2 R249.1@1625.52,229.2
NetQ3_2: Q3.2@1585.87,229.11 R236.2 | length 50
  Bottom Layer w8: R236.2@1535.87,229.11 Q3.2@1585.87,229.11
NetR1_2: R1.2 SW1.2 U2.3 U2.4 U2.5
NetR2_2: R2.2 U2.10 | length 50
  Bottom Layer w8: U2.10@1243.18,412.44 R2.2@1293.18,412.44
NetR5_1: R5.1 U3.7 | length 37.7
  Bottom Layer w12: U3.7@1067.89,727.63 1067.89,757.66 1071.89,761.66 R5.1@1071.89,763.63
NetR8_1: R8.1 U3.1 | length 43
  Bottom Layer w8: U3.1@1093.48,644.95 R8.1@1136.48,644.95
NetR9_1: R9.1 U4.3 | length 52.1
  Bottom Layer w8: R9.1@4850.49,287.13 4850.49,312.59 4853.11,315.21 4853.11,317.28 4860.92,325.09 U4.3@4870.77,325.09
NetR10_1: R10.1 R11.2 U3.6 | length 71.3
  Bottom Layer w12: R11.2@1004.7,763.63 R10.1@1038.3,763.63 1038.3,761.66 1042.3,757.66 U3.6@1042.3,727.63
NetR12_1: R12.1 U5.6 | length 28
  Bottom Layer w5: R12.1@2545.67,909.89 U5.6@2573.67,909.89
NetR13_1: R13.1 U5.13 U6.13 U8.2 | length 674.6
  Top Layer w5: v1(2499.53,679.76) 2524.57,679.76 2559.78,644.55 2583.16,644.55 v1(2626.71,688.09) 2640.26,674.55 2659.29,674.55 2668.96,684.21 2749.44,764.7 2749.44,919.41 2722.47,946.38 v1(2693.16,946.38)
  Bottom Layer w5: U6.13@2494.53,704.76 2494.53,689.19 2495.08,688.64 ; U8.2@2621.71,748.09 2621.71,730.18 2626.71,725.18 v1(2626.71,688.09) ; U5.13@2668.16,941.38 2683.73,941.38 2684.83,942.48 2689.26,942.48 v1(2693.16,946.38) ; 2495.08,688.64 2495.63,688.09 v1@2495.63,687.18 ; 2495.08,688.64 2495.08,687.73 v1@2495.63,687.18 ; v1@2495.63,687.18 2499.53,683.28 v1(2499.53,679.76) 2495.63,683.66 v1@2495.63,687.18
NetR14_1: R14.1 U5.14 U6.14 U8.3 | length 519.8
  Top Layer w5: v1(2478.78,664.76) 2478.78,682.35 2492.7,696.26 2579.13,696.26 v1(2600.96,718.09) 2600.96,741.79 2709.66,850.49 2709.66,924.14 v1(2708.16,925.64)
  Bottom Layer w5: v1(2478.78,664.76) U6.14@2478.78,704.76 ; v1(2600.96,718.09) 2600.96,725.18 2605.96,730.18 U8.3@2605.96,748.09 ; U5.14@2668.16,925.64 v1(2708.16,925.64)
NetR15_1: R15.1 U5.15 U6.15 U8.4 | length 647.7
  Top Layer w5: v1(2458.04,679.76) 2474.54,696.26 2489.27,711 2545.77,711 2575.09,740.32 2581.02,740.32 2693.16,852.47 v1(2693.16,904.89)
  Bottom Layer w5: U6.15@2463.04,704.76 2463.04,689.19 2462.49,688.64 ; U8.4@2590.21,748.09 2590.21,738.25 2575.21,723.25 R15.1@2575.21,688.09 2575.21,687.31 2569.28,681.38 2549,681.38 2515.89,648.26 2471.95,648.26 2458.04,662.18 v1(2458.04,679.76) ; U5.15@2668.16,909.89 2683.73,909.89 2684.83,908.79 2689.26,908.79 v1(2693.16,904.89) ; v1(2458.04,679.76) 2461.94,683.66 v1@2461.94,687.18 ; v1(2458.04,679.76) 2458.04,683.28 v1@2461.94,687.18 ; v1@2461.94,687.18 2462.49,687.73 2462.49,688.64 ; v1@2461.94,687.18 2461.94,688.09 2462.49,688.64
NetR16_1: R16.1 U6.6 | length 28
  Bottom Layer w5: U6.6@2463.04,799.25 R16.1@2463.04,827.25
NetR19_1: R19.1 U8.1 | length 38.2
  Bottom Layer w5: U8.1@2637.46,750.06 2637.46,740.22 2638.9,738.78 2652.46,725.22 v1(2652.46,718.1)
NetR20_1: R20.1 U10.3 | length 49.6
  Bottom Layer w10: v1(368.78,1524.51) 370.75,1524.51 375.59,1519.66 375.59,1513.88 375.67,1513.8 U10.3@375.67,1478.95
NetR23_1: R23.1 U9.3 | length 24.7
  Bottom Layer w8: R23.1@1081.93,1448.44 1081.93,1460.65 1088.82,1467.54 v1(1088.82,1470.25)
NetR23_2: R23.2 U9.1 | length 24.7
  Bottom Layer w8: v1(1014.02,1470.25) 1014.02,1467.54 1020.91,1460.65 R23.2@1020.91,1448.44
NetR24_1: R24.1 R29.2 R30.1 R32.2 U10.40 | length 148.6
  Top Layer w10: R24.1@248.15,1342.34 v1(282.52,1342.34)
  Top Layer w18: R24.1@248.15,1342.34 R29.2@248.15,1376.34 R32.2@248.15,1410.34
  Bottom Layer w8: v1(282.52,1342.34) 292.36,1342.34 307.33,1327.38 U10.40@322.52,1327.38
NetR26_1: R26.1 R27.2 U10.37 | length 131.5
  Bottom Layer w10: R27.2@282.52,1205.23 R26.1@282.52,1234.86 337.32,1234.86 355.98,1253.52 U10.37@355.98,1274.23
NetR26_2: R26.2 R28.2 U10.38 | length 107.2
  Bottom Layer w10: R28.2@250.52,1240.23 250.52,1259.52 265.23,1274.23 R26.2@282.52,1274.23 329.02,1274.23 U10.38@331.38,1276.59
NetR29_1: R29.1 R31.1 U11.5 | length 114.4
  Top Layer w10: v1@207.25,1309.87 v1(208.78,1308.34) 191.78,1308.34 v1(168.78,1331.34) 170.31,1332.88 170.31,1339.84 206.81,1376.34 R29.1@208.78,1376.34
NetR32_1: R32.1 U12.5 | length 46.1
  Top Layer w10: v1@175.61,1441.54 206.81,1410.34 R32.1@208.78,1410.34
  other v1: 169.41,1445.34
NetR34_1: R34.1 U13.24 | length 81.8
  Bottom Layer w8: R34.1@428.75,1082.11 430.72,1082.11 436.56,1076.27 436.56,1075.26 450.89,1060.93 450.89,1046.58 463.68,1033.79 U13.24@481.56,1033.79
NetR35_1: R35.1 R37.2 U13.22 | length 92.7
  Bottom Layer w8: R37.2@428.75,1014.11 R35.1@428.75,980.11 453.07,980.11 466.46,993.5 480.64,993.5 U13.22@481.56,994.42
NetR36_2: R36.2 U13.23 | length 68.1
  Bottom Layer w8: R36.2@428.75,1048.11 430.72,1048.11 436.56,1042.27 436.56,1040.3 462.76,1014.1 U13.23@481.56,1014.1
NetR38_1: R38.1 U14.19
NetR39_1: R39.1 U14.24 | length 81.8
  Bottom Layer w8: R39.1@428.75,1873.64 430.72,1873.64 436.56,1867.8 436.56,1866.78 450.89,1852.46 450.89,1838.1 463.68,1825.31 U14.24@481.56,1825.31
NetR40_1: R40.1 R42.2 U14.22 | length 92.7
  Bottom Layer w8: R42.2@428.75,1805.64 R40.1@428.75,1771.64 453.07,1771.64 466.46,1785.02 480.64,1785.02 U14.22@481.56,1785.94
NetR41_2: R41.2 U14.23 | length 68.1
  Bottom Layer w8: R41.2@428.75,1839.64 430.72,1839.64 436.56,1833.8 436.56,1831.83 462.76,1805.63 U14.23@481.56,1805.63
NetR47_1: R47.1 R48.2 U16.5 | length 206.8
  Top Layer w8: v1(1578.58,413.68) 1597.3,413.68 1629,381.98 1629,380.8 1635.53,374.28 1635.53,360.69 1647.72,348.5 1649.38,348.5 1687.63,310.25 v1(1725.29,310.25) v1@1728.89,310.25
  Bottom Layer w8: U16.5@1578.58,408.68 v1(1578.58,413.68)
NetR49_1: R49.1 R50.2
NetR51_1: R51.1 U17.2 U18.1 | length 107
  Bottom Layer w5: U17.2@1066.93,1135.76 1066.93,1145.61 1074.22,1152.9 1074.22,1159.44 1090.55,1175.76 R51.1@1092.52,1175.76 1094.49,1175.76 1103.75,1166.5 1123.52,1166.5 1134.49,1155.54 U18.1@1134.49,1150.61
NetR52_1: R52.1 U18.6 U20.5 | length 60
  Bottom Layer w8: R52.1@1288.79,1150.61 R52.1@1288.79,1151.61 U20.5@1288.79,1210.61
NetR53_1: R53.1 R56.2 U18.7
NetR54_1: R54.1 R57.2 U19.2 | length 111.3
  Top Layer w8: v1(1338.79,966.83) 1338.79,1019.54 1341.61,1022.37 v1(1341.61,1025.08)
  Bottom Layer w8: U19.2@1288.79,963.29 1331.8,963.29 1332.26,963.74 1336.49,963.74 1338.79,966.04 v1(1338.79,966.83)
NetR54_2: R54.2 R58.1 U19.1 | length 73
  Bottom Layer w8: U19.1@1288.79,988.88 R54.2@1338.79,988.88 R58.1@1361.79,988.88
NetR55_2: R55.2 U18.12 | length 58
  Bottom Layer w8: R55.2@1134.49,1017.81 R55.2@1134.49,1021.81 U18.12@1134.49,1075.81
NetR59_1: R59.1 U22.2 U23.1 | length 91.8
  Bottom Layer w8: U22.2@1223.71,1684.63 1227.58,1680.75 1227.58,1666.35 1241.49,1652.44 1241.49,1650.47 1247.33,1644.63 R59.1@1249.3,1644.63 U23.1@1289.3,1644.63
NetR60_1: R60.1 U23.6 U25.5 | length 60
  Bottom Layer w8: R60.1@1443.6,1644.63 R60.1@1443.6,1645.63 U25.5@1443.6,1704.63
NetR61_1: R61.1 R64.2 U23.7
NetR62_1: R62.1 R65.2 U24.2 | length 111.3
  Top Layer w8: v1(1493.6,1460.84) 1493.6,1463.55 1496.43,1466.38 v1(1496.43,1519.09)
  Bottom Layer w8: U24.2@1443.6,1457.3 1486.62,1457.3 1487.07,1457.76 1491.3,1457.76 1493.6,1460.06 v1(1493.6,1460.84)
NetR62_2: R62.2 R66.1 U24.1 | length 73
  Bottom Layer w8: U24.1@1443.6,1482.89 R62.2@1493.6,1482.89 R66.1@1516.6,1482.89
NetR63_2: R63.2 U23.12 | length 35
  Bottom Layer w8: R63.2@1289.3,1534.83 U23.12@1289.3,1569.83
NetR71_1: R71.1 R73.2 U27.5 | length 195.3
  Top Layer w5: v1(1505.21,650.23) 1533.15,622.29 1544.5,622.29 1566.53,600.26 1566.53,599.05 1618.78,546.8 v1(1651.92,546.8)
  Bottom Layer w5: U27.5@1505.21,645.23 v1(1505.21,650.23)
NetR72_2: R72.2 R74.1 U28.5 | length 82.6
  Bottom Layer w12: R74.1@1609.55,708.57 R72.2@1643.02,708.57 R72.2@1645.02,708.57 ; R72.2@1648.95,712.41 1645.11,708.57 R72.2@1645.02,708.57 ; U28.5@1648.95,748.57 1648.95,712.53 R72.2@1645.02,708.6
NetR75_1: R75.1 R76.2
NetR77_1: R77.1 U29.5 | length 41.7
  Bottom Layer w12: U29.5@1748.95,748.57 1748.95,712.41 1752.8,708.57 R77.1@1752.89,708.57
NetR80_2: R80.2 R81.1 U31.5 | length 77.1
  Bottom Layer w10: R81.1@1609.55,1078.57 R80.2@1643.02,1078.57 1645.02,1078.57 1648.96,1082.5 U31.5@1648.96,1118.57
NetR84_1: R84.1 R86.2 U32.5 | length 206.8
  Top Layer w8: v1(1505.21,1020.23) 1523.93,1020.23 1555.63,988.53 1555.63,987.35 1562.16,980.82 1562.16,967.24 1574.35,955.04 1576.01,955.04 1614.26,916.8 v1(1651.92,916.8) v1@1655.52,916.8
  Bottom Layer w5: U32.5@1505.21,1015.23 v1(1505.21,1020.23)
NetR85_1: R85.1 U33.5 | length 41.6
  Bottom Layer w10: U33.5@1748.95,1118.57 1748.95,1082.5 R85.1@1752.89,1078.57
NetR87_1: R87.1 R88.2
NetR90_1: R90.1 U35.4 | length 42.9
  Bottom Layer w8: v1(1674.32,1311.67) 1674.32,1321.51 1681.4,1328.59 U35.4@1681.4,1351.6
NetR91_1: R91.1 U35.3 | length 25.2
  Top Layer w8: v1(1701.09,1328.48) cw(c1702.4,1328.48) R91.1@1702.4,1329.8
  Bottom Layer w8: v1(1701.09,1328.48) U35.3@1701.09,1351.6
NetR93_1: R93.1 R94.2 U35.5 | length 206.5
  Top Layer w8: v1(1656.72,1351.6) 1656.72,1370.31 1688.42,1402.01 1689.59,1402.01 1696.12,1408.54 1709.71,1408.54 1721.9,1420.73 1721.9,1422.4 1760.14,1460.64 v1(1760.14,1498.3) v1@1760.14,1501.9
  Bottom Layer w5: v1(1656.72,1351.6) U35.5@1661.44,1351.6
NetR95_1: R95.1 R96.2
NetR99_1: R99.1 U37.16 | length 55
  Top Layer w8: R99.1@492.59,2123.97 U37.16@547.59,2123.97
NetR102_1: R102.1 U37.26 | length 65.9
  Top Layer w5: U37.26@796.61,2052.12 v1(796.61,2102.12)
  Bottom Layer w5: v1(796.61,2102.12) R102.1@796.61,2117.97
NetR103_1: R103.1 U36.6 | length 50.1
  Bottom Layer w5: U36.6@816.3,2196.02 816.3,2174.52 835.98,2154.84 R103.1@835.98,2154.05
NetR105_1: R105.1 U37.14 | length 60.1
  Top Layer w12: R105.1@487.59,2163.02 514.79,2163.02 515.11,2163.34 U37.14@547.59,2163.34
NetR106_2: R106.2 U37.7 | length 149
  Top Layer w8: R106.2@410.98,2304.68 R106.2@407.12,2308.54 409.09,2308.54 416.5,2301.14 U37.7@547.59,2301.14
NetR107_1: R107.1 U37.48 | length 50
  Top Layer w5: U37.48@986.57,2419.25 R107.1@1036.57,2419.25
NetR109_2: R109.2 U37.8 | length 146.3
  Top Layer w8: R109.2@407.12,2274.05 R109.2@409.05,2275.98 ; R109.2@410.98,2277.91 R109.2@409.05,2275.98 ; U37.8@547.59,2281.45 416.5,2281.45 411.02,2275.98 R109.2@409.05,2275.98
NetR110_2: R110.2 U37.6 | length 95.5
  Top Layer w8: v1@587.59,2320.82 U37.6@547.59,2320.82 548.32,2320.09 585.62,2320.09 588.89,2316.82 v1(591.59,2316.82)
  Bottom Layer w8: R110.2@587.59,2320.82 589.59,2318.82 R110.2@589.59,2311.78
NetR111_1: R111.1 U37.62 U40.2 | length 216.5
  Top Layer w8: U37.62@658.81,2491.1 659.26,2491.55 659.26,2526.55 v1(673.81,2541.1)
  Bottom Layer w8: U40.2@659.8,2387.75 659.8,2527.08 666,2533.29 667.97,2533.29 673.81,2539.13 v1(673.81,2541.1)
NetR112_1: R112.1 R114.1 U40.4 | length 84.6
  Bottom Layer w8: U40.4@710.98,2387.75 710.98,2429.4 715.07,2433.49 715.07,2435.45 720.91,2441.3 R112.1@747.88,2441.3
NetR113_1: R113.1 U37.63 U40.1 | length 205.4
  Top Layer w8: U37.63@639.13,2491.1 v1(639.13,2541.1)
  Bottom Layer w8: U40.1@634.21,2387.75 634.21,2536.18 v1(639.13,2541.1)
NetR114_2: R114.2 U37.61 U40.3 | length 106.2
  Top Layer w8: U37.61@678.5,2491.1 678.5,2449.01 683.51,2444 v1(683.51,2441.3)
  Bottom Layer w8: v1(683.51,2441.3) 685.39,2439.42 U40.3@685.39,2387.75
NetR117_1: R117.1 U41.3 | length 62
  Bottom Layer w8: U41.3@332.71,1962.58 359.77,1962.58 377.48,1980.3 R117.1@387.33,1980.3
NetR118_1: R118.1 SW2.3 | length 60
  Bottom Layer w12: SW2.3@110.07,888.8 R118.1@170.07,888.8
NetR127_1: R127.1 U44.24 | length 30
  Bottom Layer w5: R127.1@2378.34,479.64 U44.24@2408.34,479.64
NetR128_2: R128.2 R130.1 U44.23 | length 94.9
  Bottom Layer w5: R128.2@2351.29,420.59 R130.1@2351.29,443.59 2351.29,449.88 2351.39,449.98 2351.39,457.38 2353.96,459.96 U44.23@2408.34,459.96
NetR129_2: R129.2 R131.1 U44.18 | length 53
  Bottom Layer w9: R129.2@2434.42,302.13 R131.1@2434.42,325.13 U44.18@2434.42,355.13
NetR135_1: R135.1 U46.1 | length 1126.1
  Bottom Layer w5: U46.1@1902.13,2036.08 1879.39,2036.08 1872.54,2029.23 1818.56,2029.23 1815.63,2026.3 1815.63,2018.75 1805.34,2008.46 1779.17,2008.46 1763.07,2024.56 1763.07,2089.76 1840.16,2166.85 1840.16,2266.32 1978.84,2404.99 R135.1@2473.54,2404.99
NetR136_1: R136.1 U46.2 | length 35
  Bottom Layer w5: R136.1@1865.16,2051.83 U46.2@1900.16,2051.83
NetR137_1: R137.1 U46.3 | length 37.8
  Bottom Layer w5: R137.1@1865.16,2074.43 1872.25,2074.43 1879.1,2067.58 U46.3@1900.16,2067.58
NetR141_1: R141.1 U47.14 | length 306.7
  Bottom Layer w5: U47.14@1681.88,2192.38 1681.88,2208.58 1745.94,2272.63 1745.94,2417.35 1726.25,2437.04 R141.1@1698.86,2437.04
NetR146_1: R146.1 R148.1 R150.1 U49.11 | length 550.6
  Top Layer w5: v1(1401.02,2177.58) 1401.02,2086.1 1359.17,2044.25 1359.17,1992.84 1408.16,1943.85 1467.1,1943.85 1482.1,1928.85 1482.1,1891.77 1501.14,1872.73 1538.89,1872.73 v1(1558.83,1892.67)
  Bottom Layer w5: R150.1@1401.02,2165.49 v1(1401.02,2177.58) R146.1@1401.02,2189.66 ; v1(1558.83,1892.67) R148.1@1573.83,1892.67 U49.11@1603.83,1892.67
NetR146_2: R146.2 U50.4 | length 37.4
  Bottom Layer w5: R146.2@1401.02,2211.71 1407.32,2211.71 1413.19,2217.58 U50.4@1436.02,2217.58
NetR147_1: R147.1 U49.14 | length 35
  Bottom Layer w5: R147.1@1568.83,1951.73 U49.14@1603.83,1951.73
NetR150_2: R150.2 U51.4 | length 37.4
  Bottom Layer w5: R150.2@1401.02,2143.44 1407.32,2143.44 1413.19,2137.58 U51.4@1436.02,2137.58
NetR153_1: R153.1 U53.14 | length 35
  Bottom Layer w5: U53.14@1227.12,1945.82 R153.1@1262.12,1945.82
NetR169_2: R169.2 U54.5 | length 14.8
  Top Layer w5: v1(2801.41,1614.73) R169.2@2801.41,1629.49
NetR176_1: R176.1 U55.6 | length 30
  Bottom Layer w5: U55.6@4860.74,2402.07 R176.1@4860.74,2432.07
NetR177_1: R177.1 U55.4 | length 34.1
  Bottom Layer w8: R177.1@4831.06,2305.14 4831.06,2311.44 4840.98,2321.36 4840.98,2335.06 U55.4@4841.06,2335.14
NetR182_2: R182.2 R184.2 | length 717.8
  Top Layer w12.1: R182.2@4295.06,940 4315.06,940 cw(c4315.06,887.24) 4352.37,924.55 4412.22,864.7 cw(c4341.51,793.99) 4441.51,793.99 R184.2@4441.51,300.85
NetR183_2: R183.2 T2.1 | length 108.8
  Top Layer w12.1: T2.1@4223.02,840 4223.02,860 cw(c4243.19,860) 4243.19,880.18 4248.59,880.18 ccw(c4248.59,904.6) 4273.02,904.6 R183.2@4273.02,917.95
NetR185_1: R185.1 R187.2 | length 717.8
  Top Layer w12.1: R185.1@3891.74,300.85 3891.74,793.99 cw(c3991.74,793.99) 3921.03,864.7 3980.88,924.55 cw(c4018.19,887.24) 4018.19,940 R187.2@4037.95,940 R187.2@4038.19,940
NetR186_2: R186.2 T4.1 | length 108.8
  Top Layer w12.1: T4.1@4010,840 4010,860 cw(c4030.18,860) 4030.18,880.18 4035.58,880.18 ccw(c4035.58,904.6) 4060,904.6 R186.2@4060,917.95
NetR188_2: R188.2 R190.2 | length 717.8
  Top Layer w12.1: R188.2@4295.06,1783.94 4315.06,1783.94 ccw(c4315.06,1836.7) 4352.37,1799.39 4412.22,1859.24 ccw(c4341.51,1929.95) 4441.51,1929.95 4441.51,2392.86 R190.2@4441.51,2422.86 ; R190.2@4441.51,2423.09 R190.2@4441.51,2423.38
NetR189_2: R189.2 T6.1 | length 108.8
  Top Layer w12.1: R189.2@4273.02,1805.98 4273.02,1819.34 cw(c4297.44,1819.34) 4297.44,1843.76 4302.84,1843.76 ccw(c4302.84,1863.94) 4323.02,1863.94 T6.1@4323.02,1883.94
NetR191_1: R191.1 R193.2 | length 717.8
  Top Layer w12.1: R191.1@3891.51,2423.09 3891.51,1929.95 ccw(c3991.51,1929.95) 3920.8,1859.24 3980.65,1799.39 ccw(c4017.95,1836.7) 4017.95,1783.94 R193.2@4037.95,1783.94
NetR192_2: R192.2 T8.1 | length 108.8
  Top Layer w12.1: R192.2@4060,1805.98 4060,1819.34 cw(c4084.42,1819.34) 4084.42,1843.76 4089.82,1843.76 ccw(c4089.82,1863.94) 4110,1863.94 T8.1@4110,1883.94
NetR197_2: R197.2 U61.3 | length 37.1
  Top Layer w10: U61.3@5971.65,298.16 5986.41,298.16 5991.41,303.16 R197.2@6006.65,303.16
NetR250_1: R250.1 R251.1 | length 100
  Top Layer w5: v1(2146.26,1958.6) v1(2236.26,1958.6)
  Bottom Layer w5: R251.1@2141.26,1958.6 v1(2146.26,1958.6) ; v1(2236.26,1958.6) R250.1@2241.26,1958.6
NetR252_1: R252.1 U45.2 | length 320.1
  Bottom Layer w5: U45.2@1848.98,1847.4 1858.82,1847.4 1864.21,1852.78 1876.44,1852.78 1934.55,1910.89 2086.46,1910.89 2090.08,1914.51 R252.1@2141.26,1914.51
NetR253_1: R253.1 U45.7 | length 306.1
  Bottom Layer w5: U45.7@1971.03,1847.4 2165.91,1847.4 2219.21,1900.69 R253.1@2219.21,1936.55
NetT2_2: T2.2 U56.1 | length 77
  Top Layer w4: U56.1@4223.02,657.05 4223.02,669.42
  Top Layer w12.1: 4223.02,669.42 T2.2@4223.02,734.09
NetT4_2: T4.2 U57.1 | length 77
  Top Layer w4: U57.1@4010,657.05 4010,669.42
  Top Layer w12.1: 4010,669.42 T4.2@4010,734.09
NetT6_2: T6.2 U58.1 | length 77
  Top Layer w4: 4323.02,2054.51 U58.1@4323.02,2066.89
  Top Layer w12.1: T6.2@4323.02,1989.84 4323.02,2054.51
NetT8_2: T8.2 U59.1 | length 77
  Top Layer w4: 4110,2054.51 U59.1@4110,2066.89
  Top Layer w12.1: T8.2@4110,1989.84 4110,2054.51
NetU17_4: U17.4 U21.1 | length 466.8
  Top Layer w5: v1(1092.52,1049.15) 1223.27,1049.15 1425.82,1251.7 v1(1425.82,1271.32)
  Bottom Layer w5: v1(1425.82,1271.32) U21.1@1455.82,1271.32
NetU19_6: U19.6 U19.7 | length 25.6
  Bottom Layer w5: U19.6@1115.56,937.7 U19.7@1115.56,963.29
NetU21_2: U21.2 U22.4 | length 705.9
  Top Layer w5: v1(1198.12,1771.24) 1211.96,1757.4 1395.08,1757.4 1408.16,1744.33 1408.16,1314.58 v1(1425.82,1296.92)
  Bottom Layer w5: v1(1425.82,1296.92) U21.2@1455.82,1296.92
NetU24_6: U24.6 U24.7 | length 25.6
  Bottom Layer w5: U24.6@1270.37,1431.71 U24.7@1270.37,1457.3
NetU37_34: U37.34 U42.2 | length 635
  Top Layer w5: U37.34@986.57,2143.66 v1(1026.57,2143.66)
  Bottom Layer w5: v1(1026.57,2143.66) 990.74,2179.48 990.74,2567.35 1054.49,2631.1 U42.2@1120.82,2631.1
NetU37_38: U37.38 U38.3 | length 170.1
  Top Layer w5: U37.38@986.57,2222.4 v1(1046.57,2222.4)
  Bottom Layer w5: v1(1046.57,2222.4) 1049.06,2224.88 1055.85,2224.88 1101.79,2270.82 U38.3@1136.57,2270.82
NetU37_39: U37.39 U38.4 | length 170.1
  Top Layer w5: U37.39@986.57,2242.08 v1(1026.57,2242.08)
  Bottom Layer w5: v1(1026.57,2242.08) 1050.22,2242.08 1098.65,2290.51 U38.4@1136.57,2290.51
NetU37_40: U37.40 U38.5 | length 170.1
  Top Layer w5: U37.40@986.57,2261.77 v1(1046.57,2261.77)
  Bottom Layer w5: v1(1046.57,2261.77) 1095,2310.19 U38.5@1136.57,2310.19
NetU37_41: U37.41 U38.6 | length 170.1
  Top Layer w5: U37.41@986.57,2281.45 v1(1026.57,2281.45)
  Bottom Layer w5: v1(1026.57,2281.45) 1046.89,2281.45 1095.32,2329.88 U38.6@1136.57,2329.88
NetU37_43: U37.43 U39.3 | length 262.6
  Top Layer w5: U37.43@986.57,2320.82 v1(1026.57,2320.82)
  Bottom Layer w5: v1(1026.57,2320.82) 1051.77,2320.82 1110.82,2379.88 1110.82,2466.1 1115.55,2470.82 U39.3@1136.57,2470.82
NetU37_44: U37.44 U39.4 | length 267.4
  Top Layer w5: U37.44@986.57,2340.51 v1(1046.57,2340.51)
  Bottom Layer w5: v1(1046.57,2340.51) 1048.23,2342.17 1058.25,2342.17 1099.95,2383.87 1099.95,2478.13 1112.32,2490.51 U39.4@1136.57,2490.51
NetU37_45: U37.45 U39.5 | length 272.4
  Top Layer w5: U37.45@986.57,2360.19 v1(1026.57,2360.19)
  Bottom Layer w5: v1(1026.57,2360.19) 1054.49,2360.19 1087.39,2393.09 1087.39,2495.89 1101.69,2510.19 U39.5@1136.57,2510.19
NetU37_46: U37.46 U39.6 | length 274.7
  Top Layer w5: U37.46@986.57,2379.88 v1(1046.57,2379.88)
  Bottom Layer w5: v1(1046.57,2379.88) 1072.59,2405.9 1072.59,2512.73 1089.74,2529.88 U39.6@1136.57,2529.88
nRDY: R17.1 U7.12 U8.7 | length 353.5
  Top Layer w5: v1@2356.91,972.94 2361.55,968.3 2362.08,968.3 2393.98,936.41 2393.98,909.57 2414.41,889.14 2427.72,889.14 2465.59,851.27 2503.46,851.27 2528.17,826.56 2528.17,795.89 v1(2541.59,782.47)
  Bottom Layer w5: v1(2541.59,782.47) 2544.08,784.95 2552.27,784.95 2554.78,787.47 U8.7@2566.59,787.47
  Bottom Layer w9: v1(2351.39,972.94) 2351.39,972.16 2353.19,970.36 2353.98,970.36 2355.39,968.94 U7.12@2378.39,968.94
nRST: R18.1 U7.1 U8.8 | length 252.5
  Top Layer w5: v1@2513.63,968.94 2492.13,947.44 2492.13,904.3 2505.4,891.02 2524.54,891.02 2546.59,868.97 v1(2546.59,808.21)
  Bottom Layer w5: v1(2546.59,808.21) 2549.78,808.21 2554.78,803.21 U8.8@2566.59,803.21
  Bottom Layer w9: U7.1@2488.63,968.94 v1(2515.63,968.94)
